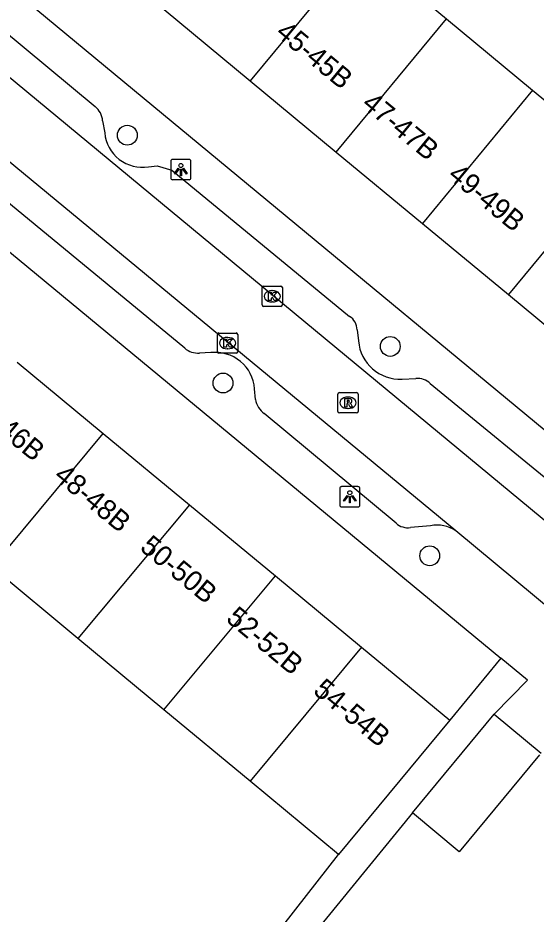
# Model space of a CAD drawing. Extents: x 162074 to 163034, y 381824 to 382557.
# Drawn here: x 162555.14 to 162580.7, y 382130.62 to 382174.8 of the extents above; entities that cross this region are included whole.
import ezdxf

# ---------------------------------------------------------------- set-up
doc = ezdxf.new("R2010")
doc.units = 0
for name, color, linetype in [('IMGEO_Boom', 7, 'Continuous'), ('IMGEO_Kolk', 7, 'Continuous'), ('IMGEO_Lichtpunt', 7, 'Continuous'), ('IMGEO_Pand', 7, 'Continuous'), ('IMGEO_Pand_nummerreeks', 7, 'Continuous'), ('IMGEO_Rijbaan_lokaal_open', 7, 'Continuous'), ('IMGEO_Rioolput', 7, 'Continuous'), ('IMGEO_Voetpad_open', 7, 'Continuous')]:
    doc.layers.add(name, color=color, linetype=linetype)

msp = doc.modelspace()

# ---------------------------------------------------------------- linework, layer by layer
at = {"layer": 'IMGEO_Boom'}
for centre in [(162560.537, 382169.018), (162573.508, 382158.604), (162565.257, 382156.799), (162575.455, 382148.282)]:
    msp.add_circle(centre, 0.489, dxfattribs=at)
at = {"layer": 'IMGEO_Kolk'}
for p, q in [((162567.183, 382160.65), (162567.183, 382161.502)), ((162567.258, 382161.576), (162568.11, 382161.576)), ((162568.184, 382161.502), (162568.184, 382160.65)), ((162567.671, 382161.356), (162567.696, 382161.356)), ((162568.11, 382160.576), (162567.258, 382160.576)), ((162567.694, 382160.796), (162567.669, 382160.796)), ((162565.057, 382159.266), (162565.909, 382159.266)), ((162564.982, 382158.34), (162564.982, 382159.192)), ((162565.47, 382159.046), (162565.495, 382159.046)), ((162565.983, 382159.192), (162565.983, 382158.34)), ((162565.493, 382158.486), (162565.468, 382158.486)), ((162565.909, 382158.266), (162565.057, 382158.266))]:
    msp.add_line(p, q, dxfattribs=at)
for points in [[(162567.183, 382160.65), (162567.183, 382161.502)], [(162567.258, 382161.576), (162568.11, 382161.576)], [(162568.184, 382161.502), (162568.184, 382160.65)], [(162567.504, 382161.276), (162567.627, 382161.276), (162567.627, 382161.125), (162567.757, 382161.276), (162567.921, 382161.276), (162567.775, 382161.125), (162567.928, 382160.876), (162567.776, 382160.876), (162567.691, 382161.04), (162567.627, 382160.973), (162567.627, 382160.876), (162567.504, 382160.876), (162567.504, 382161.276)], [(162568.11, 382160.576), (162567.258, 382160.576)], [(162565.057, 382159.266), (162565.909, 382159.266)], [(162564.982, 382158.34), (162564.982, 382159.192)], [(162565.303, 382158.966), (162565.426, 382158.966), (162565.426, 382158.815), (162565.556, 382158.966), (162565.72, 382158.966), (162565.574, 382158.815), (162565.727, 382158.566), (162565.575, 382158.566), (162565.49, 382158.73), (162565.426, 382158.663), (162565.426, 382158.566), (162565.303, 382158.566), (162565.303, 382158.966)], [(162565.983, 382159.192), (162565.983, 382158.34)], [(162565.909, 382158.266), (162565.057, 382158.266)]]:
    msp.add_lwpolyline(points, dxfattribs=at)
for centre, start, end in [((162567.26, 382161.5), 91.552, 178.448), ((162567.26, 382161.5), 91.552, 178.448), ((162568.108, 382161.5), 1.552, 88.448), ((162568.108, 382161.5), 1.552, 88.448), ((162567.26, 382160.652), 181.552, 268.448), ((162567.26, 382160.652), 181.552, 268.448), ((162568.108, 382160.652), 271.552, 358.448), ((162568.108, 382160.652), 271.552, 358.448), ((162565.059, 382159.19), 91.552, 178.448), ((162565.059, 382159.19), 91.552, 178.448), ((162565.907, 382159.19), 1.552, 88.448), ((162565.907, 382159.19), 1.552, 88.448), ((162565.059, 382158.342), 181.552, 268.448), ((162565.059, 382158.342), 181.552, 268.448), ((162565.907, 382158.342), 271.552, 358.448), ((162565.907, 382158.342), 271.552, 358.448)]:
    msp.add_arc(centre, 0.0765, start, end, dxfattribs=at)
for centre, major_axis, ratio, start_param, end_param in [((162567.67, 382161.076), (-0.387, 0.002), 0.722429, 4.712389, 7.853982), ((162567.695, 382161.076), (-0.39, 0.002), 0.717154, 1.570796, 4.712389), ((162565.469, 382158.766), (-0.387, 0.002), 0.722429, 4.712389, 7.853982), ((162565.494, 382158.766), (-0.39, 0.002), 0.717154, 1.570796, 4.712389)]:
    msp.add_ellipse(centre, major_axis=major_axis, ratio=ratio, start_param=start_param, end_param=end_param, dxfattribs=at)
at = {"layer": 'IMGEO_Lichtpunt'}
for p, q in [((162562.679, 382167.728), (162562.679, 382166.921)), ((162562.679, 382167.728), (162562.679, 382166.921)), ((162563.581, 382167.823), (162562.773, 382167.823)), ((162563.581, 382167.823), (162562.773, 382167.823)), ((162563.675, 382166.921), (162563.675, 382167.728)), ((162563.675, 382166.921), (162563.675, 382167.728)), ((162562.773, 382166.827), (162563.581, 382166.827)), ((162562.773, 382166.827), (162563.581, 382166.827)), ((162571.013, 382151.595), (162571.013, 382150.788)), ((162571.013, 382151.595), (162571.013, 382150.788)), ((162571.915, 382151.69), (162571.107, 382151.69)), ((162571.915, 382151.69), (162571.107, 382151.69)), ((162572.009, 382150.788), (162572.009, 382151.595)), ((162572.009, 382150.788), (162572.009, 382151.595)), ((162571.107, 382150.694), (162571.915, 382150.694)), ((162571.107, 382150.694), (162571.915, 382150.694))]:
    msp.add_line(p, q, dxfattribs=at)
for points in [[(162563.053, 382167.392), (162563.092, 382167.364), (162562.904, 382167.102), (162562.866, 382167.129), (162563.053, 382167.392)], [(162563.155, 382167.344), (162563.202, 382167.344), (162563.202, 382167.022), (162563.155, 382167.022), (162563.155, 382167.344)], [(162563.265, 382167.364), (162563.303, 382167.391), (162563.49, 382167.129), (162563.451, 382167.101), (162563.265, 382167.364)], [(162571.387, 382151.259), (162571.426, 382151.231), (162571.238, 382150.969), (162571.2, 382150.996), (162571.387, 382151.259)], [(162571.489, 382151.211), (162571.536, 382151.211), (162571.536, 382150.889), (162571.489, 382150.889), (162571.489, 382151.211)], [(162571.599, 382151.231), (162571.637, 382151.258), (162571.824, 382150.996), (162571.785, 382150.968), (162571.599, 382151.231)]]:
    msp.add_lwpolyline(points, dxfattribs=at)
for centre in [(162563.178, 382167.526), (162571.512, 382151.393)]:
    msp.add_circle(centre, 0.0994, dxfattribs=at)
for centre, start, end in [((162562.773, 382167.728), 90, 180), ((162562.773, 382167.728), 90, 180), ((162563.581, 382167.728), 0, 90), ((162563.581, 382167.728), 0, 90), ((162562.773, 382166.921), 180, 270), ((162562.773, 382166.921), 180, 270), ((162563.581, 382166.921), 270, 0), ((162563.581, 382166.921), 270, 360), ((162571.107, 382151.595), 90, 180), ((162571.107, 382151.595), 90, 180), ((162571.915, 382151.595), 0, 90), ((162571.915, 382151.595), 0, 90), ((162571.107, 382150.788), 180, 270), ((162571.107, 382150.788), 180, 270), ((162571.915, 382150.788), 270, 0), ((162571.915, 382150.788), 270, 360)]:
    msp.add_arc(centre, 0.0946, start, end, dxfattribs=at)
at = {"layer": 'IMGEO_Pand'}
for points in [[(162572.036, 382178.268), (162566.597, 382171.697)], [(162572.036, 382178.268), (162576.283, 382174.756)], [(162562.351, 382175.209), (162566.597, 382171.697)], [(162570.844, 382168.184), (162576.283, 382174.756)], [(162576.283, 382174.756), (162580.53, 382171.244)], [(162566.597, 382171.697), (162570.844, 382168.184)], [(162580.53, 382171.244), (162575.091, 382164.672)], [(162580.53, 382171.244), (162584.777, 382167.732)], [(162570.844, 382168.184), (162575.091, 382164.672)], [(162584.777, 382167.732), (162579.338, 382161.16)], [(162575.091, 382164.672), (162579.338, 382161.16)], [(162579.338, 382161.16), (162583.585, 382157.648)], [(162555.104, 382157.824), (162559.352, 382154.313)], [(162553.857, 382147.714), (162559.352, 382154.313)], [(162559.352, 382154.313), (162563.599, 382150.801)], [(162563.599, 382150.801), (162558.101, 382144.199)], [(162563.599, 382150.801), (162567.846, 382147.289)], [(162558.101, 382144.199), (162553.857, 382147.714)], [(162562.346, 382140.685), (162567.846, 382147.289)], [(162567.846, 382147.289), (162572.093, 382143.778)], [(162562.346, 382140.685), (162558.101, 382144.199)], [(162572.093, 382143.778), (162566.591, 382137.17)], [(162572.093, 382143.778), (162576.441, 382140.183)], [(162566.591, 382137.17), (162562.346, 382140.685)], [(162574.608, 382135.603), (162578.638, 382140.471)], [(162578.638, 382140.471), (162580.943, 382138.549)], [(162576.441, 382140.183), (162570.955, 382133.557)], [(162580.871, 382138.462), (162576.913, 382133.681), (162574.608, 382135.603)], [(162570.955, 382133.557), (162566.591, 382137.17)]]:
    msp.add_lwpolyline(points, dxfattribs=at)
at = {"layer": 'IMGEO_Rijbaan_lokaal_open'}
for points in [[(162455.575, 382254.047), (162467.743, 382243.863), (162583.48, 382148.075)], [(162576.743, 382149.513), (162505.451, 382208.42), (162453.427, 382251.529)], [(162581.599, 382145.482), (162576.743, 382149.513)]]:
    msp.add_lwpolyline(points, dxfattribs=at)
at = {"layer": 'IMGEO_Rioolput'}
for p, q in [((162570.921, 382155.4), (162570.921, 382156.252)), ((162570.996, 382156.326), (162571.848, 382156.326)), ((162571.922, 382156.252), (162571.922, 382155.4)), ((162571.409, 382156.106), (162571.434, 382156.106)), ((162571.848, 382155.326), (162570.996, 382155.326)), ((162571.432, 382155.546), (162571.407, 382155.546))]:
    msp.add_line(p, q, dxfattribs=at)
for points in [[(162570.921, 382155.4), (162570.921, 382156.252)], [(162570.996, 382156.326), (162571.848, 382156.326)], [(162571.922, 382156.252), (162571.922, 382155.4)], [(162571.51, 382156.024), (162571.258, 382156.026), (162571.258, 382155.626)], [(162571.258, 382155.626), (162571.382, 382155.626), (162571.382, 382155.788), (162571.393, 382155.788)], [(162571.436, 382155.945), (162571.382, 382155.945), (162571.382, 382155.864)], [(162571.382, 382155.864), (162571.434, 382155.864)], [(162571.44, 382155.759), (162571.511, 382155.626), (162571.651, 382155.626), (162571.586, 382155.752)], [(162571.848, 382155.326), (162570.996, 382155.326)]]:
    msp.add_lwpolyline(points, dxfattribs=at)
for centre, radius, start, end in [((162570.998, 382156.25), 0.0765, 91.552, 178.448), ((162570.998, 382156.25), 0.0765, 91.552, 178.448), ((162571.846, 382156.25), 0.0765, 1.552, 88.448), ((162571.846, 382156.25), 0.0765, 1.552, 88.448), ((162571.392, 382155.735), 0.0533, 26.0293, 88.6989), ((162571.418, 382156.053), 0.19, 274.7715, 282.9687), ((162571.442, 382155.849), 0.0964, 77.0061, 93.1865), ((162571.456, 382155.906), 0.0378, 276.6634, 79.6772), ((162571.509, 382155.914), 0.109, 350.3612, 89.416), ((162571.507, 382155.914), 0.112, 277.5842, 350.9817), ((162571.491, 382155.699), 0.108, 29.5134, 73.7905), ((162570.998, 382155.402), 0.0765, 181.552, 268.448), ((162570.998, 382155.402), 0.0765, 181.552, 268.448), ((162571.846, 382155.402), 0.0765, 271.552, 358.448), ((162571.846, 382155.402), 0.0765, 271.552, 358.448)]:
    msp.add_arc(centre, radius, start, end, dxfattribs=at)
for centre, major_axis, ratio, start_param, end_param in [((162571.408, 382155.826), (-0.387, 0.002), 0.722429, 4.712389, 7.853982), ((162571.433, 382155.826), (-0.39, 0.002), 0.717154, 1.570796, 4.712389)]:
    msp.add_ellipse(centre, major_axis=major_axis, ratio=ratio, start_param=start_param, end_param=end_param, dxfattribs=at)
at = {"layer": 'IMGEO_Voetpad_open'}
for points in [[(162585.394, 382150.935), (162530.074, 382196.697)], [(162523.638, 382188.978), (162578.962, 382143.232)], [(162515.662, 382179.338), (162506.038, 382167.712), (162561.785, 382121.807), (162570.955, 382133.557)], [(162549.686, 382178.119), (162558.944, 382170.438)], [(162559.316, 382169.728), (162559.422, 382169.131)], [(162563.367, 382158.514), (162552.146, 382167.758)], [(162561.577, 382167.463), (162562.002, 382167.503), (162562.729, 382167.298), (162571.501, 382160.086)], [(162571.868, 382159.425), (162571.937, 382158.874)], [(162564.661, 382158.297), (162564.095, 382158.269)], [(162574.089, 382156.986), (162574.773, 382157.029)], [(162575.482, 382156.776), (162582.465, 382151.06)], [(162566.855, 382155.982), (162566.814, 382156.516)], [(162573.794, 382149.886), (162567.284, 382155.29)], [(162575.5, 382149.764), (162574.506, 382149.676)], [(162578.962, 382143.232), (162576.441, 382140.183)], [(162578.638, 382140.471), (162580.273, 382142.148), (162578.962, 382143.232)], [(162574.608, 382135.603), (162568.094, 382127.642), (162566.723, 382126.041)]]:
    msp.add_lwpolyline(points, dxfattribs=at)
for centre, radius, start, end in [((162558.34, 382169.669), 0.978, 3.4617, 51.8424), ((162561.278, 382169.303), 1.864, 185.294, 279.2253), ((162571.098, 382159.43), 0.77, 359.6412, 58.4386), ((162574.006, 382159.062), 2.077, 185.184, 272.2935), ((162564.065, 382159.385), 1.116, 231.2761, 271.5238), ((162564.885, 382156.376), 1.934, 4.1544, 96.6493), ((162574.831, 382156.071), 0.96, 47.2812, 93.4419), ((162568.013, 382156.221), 1.182, 191.6571, 231.936), ((162574.371, 382150.532), 0.866, 228.2031, 278.9307), ((162575.821, 382148.15), 1.645, 55.916, 101.2514)]:
    msp.add_arc(centre, radius, start, end, dxfattribs=at)

# ---------------------------------------------------------------- texts
at = {"layer": 'IMGEO_Pand_nummerreeks'}
for s, rotation, p in [('45-45B', 320.4088, (162567.8, 382173.972)), ('47-47B', 320.4088, (162572.047, 382170.46)), ('49-49B', 320.4088, (162576.294, 382166.947)), ('46-46B', 320.4159, (162552.611, 382155.63)), ('48-48B', 320.4159, (162556.858, 382152.118)), ('50-50B', 320.4159, (162561.106, 382148.607)), ('52-52B', 320.4159, (162565.353, 382145.095)), ('54-54B', 320.4159, (162569.65, 382141.542))]:
    msp.add_text(s, height=1, rotation=rotation, dxfattribs=at).set_placement(p)

doc.saveas('drawing.dxf')
